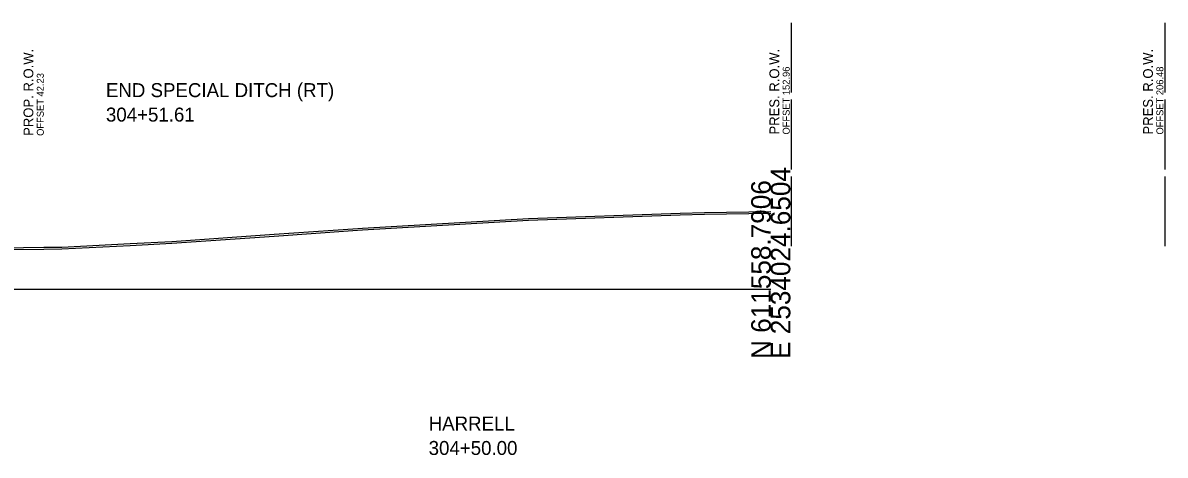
# Model space of a CAD drawing. Extents: x -192 to 2669, y -25 to 8040.
# Drawn here: x 192.9 to 356.5, y 5976.2 to 6038.1 of the extents above; entities that cross this region are included whole.
import ezdxf

# ---------------------------------------------------------------- set-up
doc = ezdxf.new("R2010")
doc.units = 0
for name, color, linetype in [('DESIGN - ROW - Right-of-Way and Easement Labels', 7, 'Continuous'), ('DESIGN - SHEET - Light Grid', 7, 'Continuous'), ('DESIGN - TRANSPORTATION - Text', 7, 'Continuous'), ('DESIGN - TYPICAL - Warning Text', 7, 'Continuous'), ('SURVEY - GROUND - Bottom of Topsoil Layer', 7, 'Continuous'), ('SURVEY - GROUND - Top of Ground', 7, 'Continuous'), ('SURVEY - PROPERTY - ROW Lines', 7, 'Continuous'), ('SURVEY - PROPERTY - ROW Lines Text', 7, 'Continuous')]:
    doc.layers.add(name, color=color, linetype=linetype)

msp = doc.modelspace()

# ---------------------------------------------------------------- linework, layer by layer
at = {"layer": 'DESIGN - SHEET - Light Grid'}
msp.add_line((150, 6000), (300, 6000), dxfattribs=at)
at = {"layer": 'SURVEY - GROUND - Bottom of Topsoil Layer'}
for p, q in [((290.49, 6010.72), (300, 6010.89)), ((241.53, 6008.47), (265.31, 6009.89)), ((265.31, 6009.89), (287.04, 6010.62)), ((287.04, 6010.62), (290.49, 6010.72)), ((228.87, 6007.61), (240.16, 6008.38)), ((240.16, 6008.38), (241.53, 6008.47)), ((198.48, 6005.78), (208.27, 6006.27)), ((208.27, 6006.27), (214.21, 6006.59)), ((214.21, 6006.59), (228.87, 6007.61)), ((187.11, 6005.64), (195.89, 6005.74)), ((195.89, 6005.74), (198.48, 6005.78))]:
    msp.add_line(p, q, dxfattribs=at)
at = {"layer": 'SURVEY - GROUND - Top of Ground'}
msp.add_lwpolyline([(187.11, 6005.89), (195.89, 6005.99), (198.48, 6006.03), (208.27, 6006.52), (214.21, 6006.84), (228.87, 6007.86), (240.16, 6008.63), (241.53, 6008.72), (265.31, 6010.14), (287.04, 6010.87), (290.49, 6010.97), (300, 6011.14)], dxfattribs=at)
at = {"layer": 'SURVEY - PROPERTY - ROW Lines'}
for p, q in [((302.96, 6028.14), (302.96, 6038.14)), ((356.48, 6028.14), (356.48, 6038.14)), ((302.96, 6017.14), (302.96, 6027.14)), ((356.48, 6017.14), (356.48, 6027.14)), ((302.96, 6006.14), (302.96, 6016.14)), ((356.48, 6006.14), (356.48, 6016.14))]:
    msp.add_line(p, q, dxfattribs=at)

# ---------------------------------------------------------------- texts
at = {"layer": 'DESIGN - ROW - Right-of-Way and Easement Labels'}
for s, height, p in [('PROP. R.O.W.', 1.4, (194.38, 6021.95)), ('OFFSET 42.23', 1, (195.88, 6021.95))]:
    msp.add_text(s, height=height, rotation=90, dxfattribs=at).set_placement(p)
at = {"layer": 'DESIGN - SHEET - Light Grid'}
for s, p in [('E 2534024.6504', (302.8, 5990)), ('N 611558.7906', (300, 5990))]:
    msp.add_text(s, height=2.8, rotation=90, dxfattribs=at).set_placement(p)
at = {"layer": 'DESIGN - TRANSPORTATION - Text'}
for s, p in [('END SPECIAL DITCH (RT)', (204.78, 6027.5)), ('304+51.61', (204.78, 6024))]:
    msp.add_text(s, height=2, dxfattribs=at).set_placement(p)
at = {"layer": 'DESIGN - TYPICAL - Warning Text'}
for s, p in [('HARRELL', (251, 5979.75)), ('304+50.00', (251, 5976.25))]:
    msp.add_text(s, height=2, dxfattribs=at).set_placement(p)
at = {"layer": 'SURVEY - PROPERTY - ROW Lines Text'}
for s, height, p in [('PRES. R.O.W.', 1.4, (301.21, 6022.14)), ('PRES. R.O.W.', 1.4, (354.73, 6022.14)), ('OFFSET 152.96', 1, (302.71, 6022.14)), ('OFFSET 206.48', 1, (356.23, 6022.14))]:
    msp.add_text(s, height=height, rotation=90, dxfattribs=at).set_placement(p)

doc.saveas('drawing.dxf')
